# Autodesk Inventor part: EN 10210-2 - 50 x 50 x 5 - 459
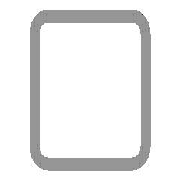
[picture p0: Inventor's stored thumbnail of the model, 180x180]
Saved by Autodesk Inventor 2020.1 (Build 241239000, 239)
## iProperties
_CCFamilyMember: 16
_CCFamilyDisplayName: DIN EN 10210-2 (USAS B17.1 quadratisch) - Rohrleitung — In Klammern angegebene Größen wurden aufgehoben
_FrameMemberDoc: Frame Member File
_Version: 15.0.0
_GetPNFromCC: 1
Created: 2019-01
Part Number: EN 10210-2 - 50 x 50 x 5 - 459
Material: Stahl, weich
Description: Rohrleitung
Document SubType Name: Modeling
Standard: DIN
Designer: lutzd
Standard Revision: 2006-07
Standards Organization: DIN
Language: de-DE
Size Designation: 50 x 50 x 5
Categories: <MemberInstance><Categories><Category DisplayName="Profile" InternalName="089c4875-fa83-4c05-b084-43b9cc11f5ed" Mnemonic="GRDR"><CategoryParameter DisplayName="
Stock Number: 50 x 50 x 5
Mass: 3146.18 g
Surface Area: 1571.36 cm^2
Volume: 400.787 cm^3
Density: 7.85 g/cm^3
Appearance: Halbpoliert
G_W: 50,000 mm
G_H: 50,000 mm
DocNumber: ADSK-014207
Folder: .
Dimensions: 50x50x459 mm
Mass: 3,146 kg
+0358B9B5-7DB1-41C3-8D8C-3EA06F80352F+SCHNITTDETAIL1: Schnittwinkel 90,00 grd
+297A2670-C07C-4FC2-AAF5-BF8116A6DEE9+SCHNITTDETAIL2: Schnittwinkel 90,00 grd
G_L: 459,000 mm
IsCustomPart: 1
Title: Profil-Bauteil
Author: lutzd
Revision Number: -
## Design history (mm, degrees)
node "Startebene"
node "Endebene"
sketch "Skizze"
  geometry: L1 (-25, -17.5)-(-25, 17.5); L2 (-17.5, 25)-(17.5, 25); L3 (25, 17.5)-(25, -17.5); L4 (17.5, -25)-(-17.5, -25); L5 (-15, 20)-(15, 20); L6 (20, 15)-(20, -15); L7 (15, -20)-(-15, -20); L8 (-20, -15)-(-20, 15); L9 (0, 37.175)-(0, -37.175) reference; L10 (-37.175, 0)-(37.175, 0) reference; A1 r 7.5 centre (-17.5, -17.5) between (-25, -17.5) and (-17.5, -25); A2 r 7.5 centre (-17.5, 17.5) between (-17.5, 25) and (-25, 17.5); A3 r 7.5 centre (17.5, 17.5) between (25, 17.5) and (17.5, 25); A4 r 7.5 centre (17.5, -17.5) between (17.5, -25) and (25, -17.5); A5 r 5 centre (-15, -15) between (-20, -15) and (-15, -20); A6 r 5 centre (-15, 15) between (-15, 20) and (-20, 15); A7 r 5 centre (15, 15) between (20, 15) and (15, 20); A8 r 5 centre (15, -15) between (15, -20) and (20, -15)
  constraints: 16 end point, 16 point on circle, 16 tangent, 8 centre point, 6 equal radius, 4 parallel, 2 perpendicular, 2 other
  dimensions: "d7" = 7.5 radius of A1 (= G_IR); "d10" = 50 distance between parallel lines of L2 L4 (= G_H); "d11" = 50 distance between parallel lines of L1 L3 (= G_W); "d12" = 5 distance between parallel lines of L3 L6 (= G_T); "d15" = 25 distance between parallel lines of L2 L10 (= 0.5 x d10); "d16" = 25 distance between parallel lines of L9 L3 (= 0.5 x d11); "d19" = 5 radius of A5 (= G_T); "d20" = 5 distance between parallel lines of L4 L7 (= G_T)
extrude "Körper" new body sketch "Skizze" stored distance "d3" = 459 (= G_L); taper "d4" = 0 deg
node "Driven Length"
  sketch "Sketch3"
    geometry: L1 (0, 0)-(10, 0) reference
    constraints: 2 end point, 1 horizontal
  workplane "Work Plane3"
  sketch "Sketch4"
    geometry: L1 (-2, 50)-(12, 50) reference; L2 (-2, 509)-(12, 509) reference
    dimensions: "d18" = 459 distance between parallel lines of L1 L2 (derived)
workplane "Arbeitsebene4"
feature "Trennen1"
workplane "Arbeitsebene5"
feature "Trennen2"
body "Solid1"
other parameters: "G_W" = 50 [user parameter; used in 1 equation term], "G_H" = 50 [user parameter; used in 1 equation term], "G_T" = 5 [user parameter; used in 3 equation terms], "G_IR" = 7.5 [user parameter; used in 1 equation term], "G_L" = 459 (= d18) [user parameter; used in 1 equation term], "d14" = 509 (= G_OFFSET_END + B_L), "B_L" = 559 [user parameter; used in 1 equation term], "d17" = 90 deg
